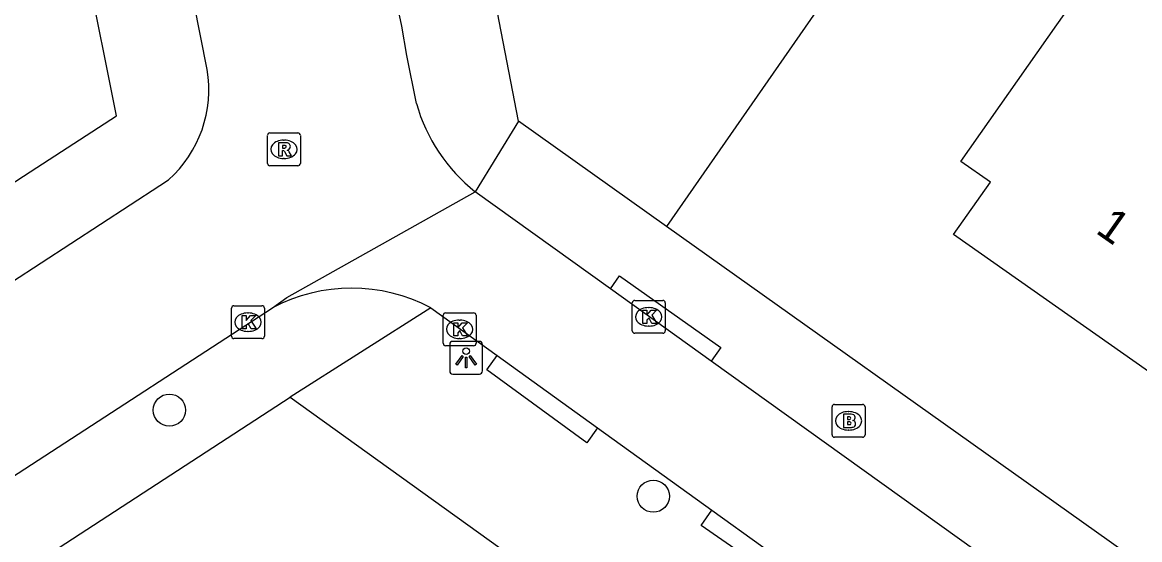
# Model space of a CAD drawing. Extents: x 161772 to 163123, y 383092 to 383917.
# Drawn here: x 162605.53 to 162639.5, y 383823.67 to 383839.41 of the extents above; entities that cross this region are included whole.
import ezdxf

# ---------------------------------------------------------------- set-up
doc = ezdxf.new("R2010")
doc.units = 0
for name, color, linetype in [('IMGEO_Boom', 7, 'Continuous'), ('IMGEO_Brandkraan', 7, 'Continuous'), ('IMGEO_Groenvoorziening', 7, 'Continuous'), ('IMGEO_Kolk', 7, 'Continuous'), ('IMGEO_Lichtpunt', 7, 'Continuous'), ('IMGEO_Pand', 7, 'Continuous'), ('IMGEO_Pand_nummerreeks', 7, 'Continuous'), ('IMGEO_Rijbaan_lokaal_open', 7, 'Continuous'), ('IMGEO_Rioolput', 7, 'Continuous'), ('IMGEO_Voetpad_open', 7, 'Continuous')]:
    doc.layers.add(name, color=color, linetype=linetype)

msp = doc.modelspace()

# ---------------------------------------------------------------- linework, layer by layer
at = {"layer": 'IMGEO_Boom'}
for centre in [(162610.003, 383827.611), (162624.716, 383824.991)]:
    msp.add_circle(centre, 0.489, dxfattribs=at)
at = {"layer": 'IMGEO_Brandkraan'}
for p, q in [((162630.151, 383826.86), (162630.151, 383827.712)), ((162630.226, 383827.786), (162631.078, 383827.786)), ((162630.639, 383827.566), (162630.664, 383827.566)), ((162631.152, 383827.712), (162631.152, 383826.86)), ((162631.078, 383826.786), (162630.226, 383826.786)), ((162630.662, 383827.006), (162630.637, 383827.006))]:
    msp.add_line(p, q, dxfattribs=at)
for points in [[(162630.151, 383826.86), (162630.151, 383827.712)], [(162630.226, 383827.786), (162631.078, 383827.786)], [(162630.499, 383827.486), (162630.499, 383827.086), (162630.712, 383827.086)], [(162630.73, 383827.486), (162630.499, 383827.486)], [(162631.152, 383827.712), (162631.152, 383826.86)], [(162630.678, 383827.405), (162630.624, 383827.405), (162630.624, 383827.329)], [(162630.624, 383827.329), (162630.677, 383827.329)], [(162630.686, 383827.253), (162630.624, 383827.253), (162630.624, 383827.172)], [(162630.624, 383827.172), (162630.686, 383827.172)], [(162631.078, 383826.786), (162630.226, 383826.786)]]:
    msp.add_lwpolyline(points, dxfattribs=at)
for centre, radius, start, end in [((162630.228, 383827.71), 0.0765, 91.552, 178.448), ((162630.228, 383827.71), 0.0765, 91.552, 178.448), ((162630.734, 383827.341), 0.145, 59.4692, 91.5367), ((162630.759, 383827.388), 0.0922, 285.5137, 58.1501), ((162631.076, 383827.71), 0.0765, 1.552, 88.448), ((162631.076, 383827.71), 0.0765, 1.552, 88.448), ((162630.679, 383827.367), 0.0379, 267.8285, 90.9355), ((162630.687, 383827.212), 0.0404, 269.8759, 90.5077), ((162630.764, 383827.196), 0.105, 301.3115, 78.989), ((162630.228, 383826.862), 0.0765, 181.552, 268.448), ((162630.228, 383826.862), 0.0765, 181.552, 268.448), ((162630.718, 383827.337), 0.251, 268.6676, 293.5347), ((162631.076, 383826.862), 0.0765, 271.552, 358.448), ((162631.076, 383826.862), 0.0765, 271.552, 358.448)]:
    msp.add_arc(centre, radius, start, end, dxfattribs=at)
for centre, major_axis, ratio, start_param, end_param in [((162630.638, 383827.286), (-0.387, 0.002), 0.722429, 4.712389, 7.853982), ((162630.663, 383827.286), (-0.39, 0.002), 0.717154, 1.570796, 4.712389)]:
    msp.add_ellipse(centre, major_axis=major_axis, ratio=ratio, start_param=start_param, end_param=end_param, dxfattribs=at)
at = {"layer": 'IMGEO_Groenvoorziening'}
msp.add_lwpolyline([(162633.386, 383845.1), (162625.12, 383833.199)], dxfattribs=at)
at = {"layer": 'IMGEO_Kolk'}
for p, q in [((162624.077, 383830.024), (162624.077, 383830.876)), ((162624.152, 383830.95), (162625.004, 383830.95)), ((162625.078, 383830.876), (162625.078, 383830.024)), ((162611.892, 383829.861), (162611.892, 383830.713)), ((162611.967, 383830.787), (162612.819, 383830.787)), ((162612.38, 383830.567), (162612.405, 383830.567)), ((162612.893, 383830.713), (162612.893, 383829.861)), ((162618.401, 383830.57), (162619.253, 383830.57)), ((162624.565, 383830.73), (162624.59, 383830.73)), ((162618.326, 383829.644), (162618.326, 383830.496)), ((162618.814, 383830.35), (162618.839, 383830.35)), ((162619.327, 383830.496), (162619.327, 383829.644)), ((162624.588, 383830.17), (162624.563, 383830.17)), ((162612.403, 383830.007), (162612.378, 383830.007)), ((162625.004, 383829.95), (162624.152, 383829.95)), ((162612.819, 383829.787), (162611.967, 383829.787)), ((162619.253, 383829.57), (162618.401, 383829.57)), ((162618.837, 383829.79), (162618.812, 383829.79))]:
    msp.add_line(p, q, dxfattribs=at)
for points in [[(162624.077, 383830.024), (162624.077, 383830.876)], [(162624.152, 383830.95), (162625.004, 383830.95)], [(162625.078, 383830.876), (162625.078, 383830.024)], [(162611.892, 383829.861), (162611.892, 383830.713)], [(162611.967, 383830.787), (162612.819, 383830.787)], [(162612.893, 383830.713), (162612.893, 383829.861)], [(162618.401, 383830.57), (162619.253, 383830.57)], [(162624.398, 383830.65), (162624.521, 383830.65), (162624.521, 383830.499), (162624.651, 383830.65), (162624.815, 383830.65), (162624.669, 383830.499), (162624.822, 383830.25), (162624.67, 383830.25), (162624.585, 383830.414), (162624.521, 383830.347), (162624.521, 383830.25), (162624.398, 383830.25), (162624.398, 383830.65)], [(162612.213, 383830.487), (162612.336, 383830.487), (162612.336, 383830.336), (162612.466, 383830.487), (162612.63, 383830.487), (162612.484, 383830.336), (162612.637, 383830.087), (162612.485, 383830.087), (162612.4, 383830.251), (162612.336, 383830.184), (162612.336, 383830.087), (162612.213, 383830.087), (162612.213, 383830.487)], [(162618.326, 383829.644), (162618.326, 383830.496)], [(162618.647, 383830.27), (162618.77, 383830.27), (162618.77, 383830.119), (162618.9, 383830.27), (162619.064, 383830.27), (162618.918, 383830.119), (162619.071, 383829.87), (162618.919, 383829.87), (162618.834, 383830.034), (162618.77, 383829.967), (162618.77, 383829.87), (162618.647, 383829.87), (162618.647, 383830.27)], [(162619.327, 383830.496), (162619.327, 383829.644)], [(162625.004, 383829.95), (162624.152, 383829.95)], [(162612.819, 383829.787), (162611.967, 383829.787)], [(162619.253, 383829.57), (162618.401, 383829.57)]]:
    msp.add_lwpolyline(points, dxfattribs=at)
for centre, start, end in [((162624.154, 383830.874), 91.552, 178.448), ((162624.154, 383830.874), 91.552, 178.448), ((162625.002, 383830.874), 1.552, 88.448), ((162625.002, 383830.874), 1.552, 88.448), ((162611.969, 383830.711), 91.552, 178.448), ((162611.969, 383830.711), 91.552, 178.448), ((162612.817, 383830.711), 1.552, 88.448), ((162612.817, 383830.711), 1.552, 88.448), ((162618.403, 383830.494), 91.552, 178.448), ((162618.403, 383830.494), 91.552, 178.448), ((162619.251, 383830.494), 1.552, 88.448), ((162619.251, 383830.494), 1.552, 88.448), ((162611.969, 383829.863), 181.552, 268.448), ((162611.969, 383829.863), 181.552, 268.448), ((162612.817, 383829.863), 271.552, 358.448), ((162612.817, 383829.863), 271.552, 358.448), ((162624.154, 383830.026), 181.552, 268.448), ((162624.154, 383830.026), 181.552, 268.448), ((162625.002, 383830.026), 271.552, 358.448), ((162625.002, 383830.026), 271.552, 358.448), ((162618.403, 383829.646), 181.552, 268.448), ((162618.403, 383829.646), 181.552, 268.448), ((162619.251, 383829.646), 271.552, 358.448), ((162619.251, 383829.646), 271.552, 358.448)]:
    msp.add_arc(centre, 0.0765, start, end, dxfattribs=at)
for centre, major_axis, ratio, start_param, end_param in [((162612.379, 383830.287), (-0.387, 0.002), 0.722429, 4.712389, 7.853982), ((162612.404, 383830.287), (-0.39, 0.002), 0.717154, 1.570796, 4.712389), ((162624.564, 383830.45), (-0.387, 0.002), 0.722429, 4.712389, 7.853982), ((162624.589, 383830.45), (-0.39, 0.002), 0.717154, 1.570796, 4.712389), ((162618.813, 383830.07), (-0.387, 0.002), 0.722429, 4.712389, 7.853982), ((162618.838, 383830.07), (-0.39, 0.002), 0.717154, 1.570796, 4.712389)]:
    msp.add_ellipse(centre, major_axis=major_axis, ratio=ratio, start_param=start_param, end_param=end_param, dxfattribs=at)
at = {"layer": 'IMGEO_Lichtpunt'}
for p, q in [((162618.527, 383829.609), (162618.527, 383828.802)), ((162618.527, 383829.609), (162618.527, 383828.802)), ((162619.429, 383829.704), (162618.621, 383829.704)), ((162619.429, 383829.704), (162618.621, 383829.704)), ((162619.523, 383828.802), (162619.523, 383829.609)), ((162619.523, 383828.802), (162619.523, 383829.609)), ((162618.621, 383828.708), (162619.429, 383828.708)), ((162618.621, 383828.708), (162619.429, 383828.708))]:
    msp.add_line(p, q, dxfattribs=at)
for points in [[(162618.901, 383829.273), (162618.94, 383829.245), (162618.752, 383828.983), (162618.714, 383829.01), (162618.901, 383829.273)], [(162619.003, 383829.225), (162619.05, 383829.225), (162619.05, 383828.903), (162619.003, 383828.903), (162619.003, 383829.225)], [(162619.113, 383829.245), (162619.151, 383829.272), (162619.338, 383829.01), (162619.299, 383828.982), (162619.113, 383829.245)]]:
    msp.add_lwpolyline(points, dxfattribs=at)
msp.add_circle((162619.026, 383829.407), 0.0994, dxfattribs=at)
for centre, start, end in [((162618.621, 383829.609), 90, 180), ((162618.621, 383829.609), 90, 180), ((162619.429, 383829.609), 0, 90), ((162619.429, 383829.609), 0, 90), ((162618.621, 383828.802), 180, 270), ((162618.621, 383828.802), 180, 270), ((162619.429, 383828.802), 270, 0), ((162619.429, 383828.802), 270, 360)]:
    msp.add_arc(centre, 0.0946, start, end, dxfattribs=at)
at = {"layer": 'IMGEO_Pand'}
msp.add_lwpolyline([(162639.806, 383828.602), (162639.774, 383828.787), (162633.844, 383832.956), (162634.964, 383834.549), (162634.068, 383835.179), (162636.988, 383839.332), (162638.788, 383841.893), (162639.309, 383841.526), (162639.712, 383842.1), (162639.518, 383842.236), (162641.304, 383844.777), (162644.492, 383842.535), (162644.352, 383842.336), (162647.651, 383840.016)], dxfattribs=at)
at = {"layer": 'IMGEO_Rijbaan_lokaal_open'}
for points in [[(162611.151, 383837.971), (162607.333, 383857.297)], [(162617.513, 383836.94), (162617.224, 383838.405), (162617.075, 383839.295), (162616.668, 383841.212), (162616.408, 383842.427)], [(162601.586, 383829.152), (162609.711, 383834.441), (162609.981, 383834.617)], [(162613.136, 383830.727), (162613.575, 383831.038), (162619.304, 383834.256)], [(162623.417, 383831.304), (162619.304, 383834.256)], [(162626.476, 383829.105), (162623.417, 383831.304)], [(162600.907, 383822.768), (162612.326, 383830.2), (162613.136, 383830.727)], [(162617.954, 383830.722), (162619.967, 383829.273)], [(162619.967, 383829.273), (162623.024, 383827.071)], [(162658.236, 383806.306), (162648.981, 383812.956), (162626.476, 383829.105)], [(162623.024, 383827.071), (162626.499, 383824.569)], [(162626.499, 383824.569), (162629.6, 383822.336)]]:
    msp.add_lwpolyline(points, dxfattribs=at)
for centre, radius, start, end in [((162607.511, 383837.36), 3.691, 312.0065, 9.5321), ((162622.538, 383838.354), 5.22, 195.7113, 231.7181), ((162615.54, 383826.167), 5.155, 62.0808, 117.8003)]:
    msp.add_arc(centre, radius, start, end, dxfattribs=at)
at = {"layer": 'IMGEO_Rioolput'}
for p, q in [((162612.985, 383835.12), (162612.985, 383835.972)), ((162613.06, 383836.046), (162613.912, 383836.046)), ((162613.986, 383835.972), (162613.986, 383835.12)), ((162613.473, 383835.826), (162613.498, 383835.826)), ((162613.496, 383835.266), (162613.471, 383835.266)), ((162613.912, 383835.046), (162613.06, 383835.046))]:
    msp.add_line(p, q, dxfattribs=at)
for points in [[(162612.985, 383835.12), (162612.985, 383835.972)], [(162613.06, 383836.046), (162613.912, 383836.046)], [(162613.986, 383835.972), (162613.986, 383835.12)], [(162613.574, 383835.744), (162613.322, 383835.746), (162613.322, 383835.346)], [(162613.5, 383835.665), (162613.446, 383835.665), (162613.446, 383835.584)], [(162613.322, 383835.346), (162613.446, 383835.346), (162613.446, 383835.508), (162613.457, 383835.508)], [(162613.446, 383835.584), (162613.498, 383835.584)], [(162613.504, 383835.479), (162613.575, 383835.346), (162613.715, 383835.346), (162613.65, 383835.472)], [(162613.912, 383835.046), (162613.06, 383835.046)]]:
    msp.add_lwpolyline(points, dxfattribs=at)
for centre, radius, start, end in [((162613.062, 383835.97), 0.0765, 91.552, 178.448), ((162613.062, 383835.97), 0.0765, 91.552, 178.448), ((162613.91, 383835.97), 0.0765, 1.552, 88.448), ((162613.91, 383835.97), 0.0765, 1.552, 88.448), ((162613.506, 383835.569), 0.0964, 77.0061, 93.1865), ((162613.52, 383835.626), 0.0378, 276.6634, 79.6772), ((162613.573, 383835.634), 0.109, 350.3612, 89.416), ((162613.571, 383835.634), 0.112, 277.5842, 350.9817), ((162613.456, 383835.455), 0.0533, 26.0293, 88.6989), ((162613.482, 383835.773), 0.19, 274.7715, 282.9687), ((162613.555, 383835.419), 0.108, 29.5134, 73.7905), ((162613.062, 383835.122), 0.0765, 181.552, 268.448), ((162613.062, 383835.122), 0.0765, 181.552, 268.448), ((162613.91, 383835.122), 0.0765, 271.552, 358.448), ((162613.91, 383835.122), 0.0765, 271.552, 358.448)]:
    msp.add_arc(centre, radius, start, end, dxfattribs=at)
for centre, major_axis, ratio, start_param, end_param in [((162613.472, 383835.546), (-0.387, 0.002), 0.722429, 4.712389, 7.853982), ((162613.497, 383835.546), (-0.39, 0.002), 0.717154, 1.570796, 4.712389)]:
    msp.add_ellipse(centre, major_axis=major_axis, ratio=ratio, start_param=start_param, end_param=end_param, dxfattribs=at)
at = {"layer": 'IMGEO_Voetpad_open'}
for points in [[(162604.083, 383833.762), (162605.97, 383834.99), (162608.398, 383836.57), (162607.494, 383841.076), (162604.303, 383856.977)], [(162620.62, 383836.4), (162619.915, 383840.025)], [(162620.62, 383836.4), (162619.304, 383834.256)], [(162625.12, 383833.199), (162620.62, 383836.4)], [(162736.047, 383754.285), (162625.12, 383833.199)], [(162623.417, 383831.304), (162623.692, 383831.693), (162626.764, 383829.513), (162626.476, 383829.105)], [(162617.954, 383830.722), (162613.678, 383828.007)], [(162623.024, 383827.071), (162622.691, 383826.614), (162619.65, 383828.837), (162619.967, 383829.273)], [(162567.812, 383798.14), (162613.678, 383828.007)], [(162613.678, 383828.007), (162637.23, 383811.064), (162657.832, 383796.659), (162723.086, 383750), (162726.651, 383747.451)], [(162629.6, 383822.336), (162629.314, 383821.921), (162626.173, 383824.098), (162626.499, 383824.569)]]:
    msp.add_lwpolyline(points, dxfattribs=at)

# ---------------------------------------------------------------- texts
at = {"layer": 'IMGEO_Pand_nummerreeks'}
msp.add_text('1', height=1, rotation=324.8914, dxfattribs=at).set_placement((162638.127, 383833.026))

doc.saveas('drawing.dxf')
